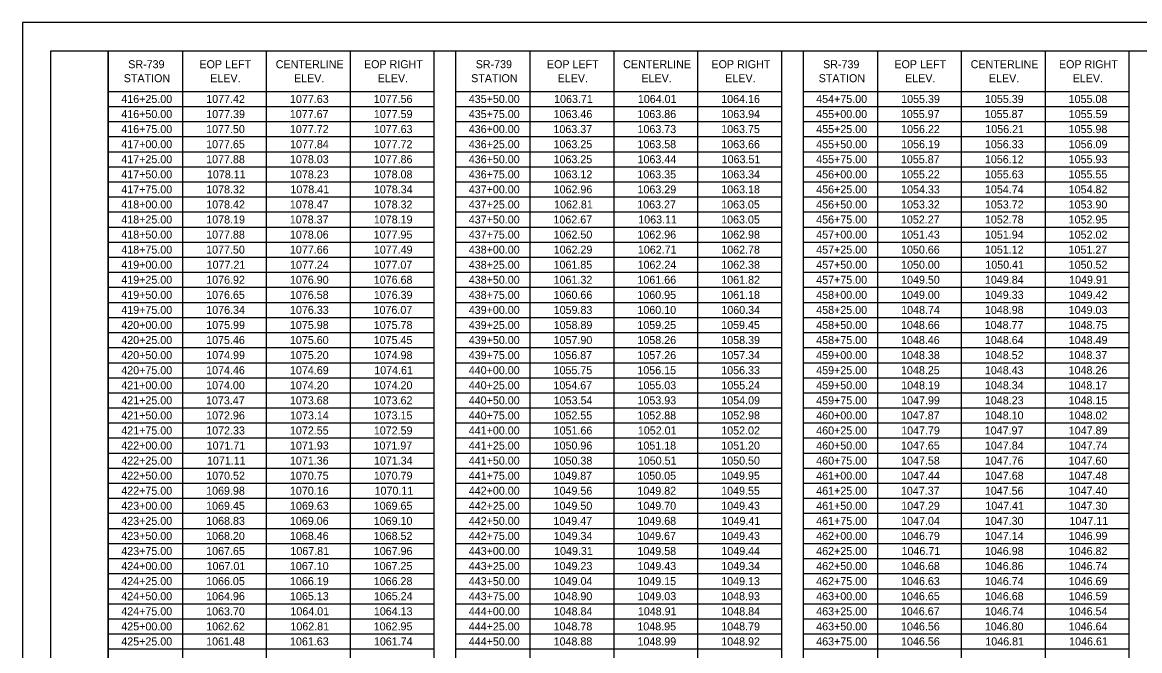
# Model space of a CAD drawing. Extents: x 0 to 34, y 0 to 22.
# Drawn here: x 0 to 19.54, y 11.01 to 22 of the extents above; entities that cross this region are included whole.
import ezdxf

# ---------------------------------------------------------------- set-up
doc = ezdxf.new("R2010")
doc.units = 0
for name, color, linetype in [('SH_Border', 7, 'Continuous'), ('SH_Cut_Line', 7, 'Continuous'), ('SH_Text', 7, 'Continuous')]:
    doc.layers.add(name, color=color, linetype=linetype)

msp = doc.modelspace()

# ---------------------------------------------------------------- linework, layer by layer
at = {"layer": 'SH_Border'}
for points in [[(0.5, 21.5), (1.5, 21.5), (1.5, 0.5), (0.5, 0.5)], [(1.5, 21.5), (33.5, 21.5), (33.5, 0.5), (1.5, 0.5)]]:
    msp.add_lwpolyline(points, close=True, dxfattribs=at)
at = {"layer": 'SH_Cut_Line'}
msp.add_lwpolyline([(0, 0), (34, 0), (34, 22), (0, 22)], close=True, dxfattribs=at)
at = {"layer": 'SH_Text'}
for p, q in [((1.5, 21.5), (7.199, 21.5)), ((1.5, 21.5), (1.5, 0.5)), ((2.801, 21.5), (2.801, 0.5)), ((4.267, 21.5), (4.267, 0.5)), ((5.733, 21.5), (5.733, 0.5)), ((7.199, 21.5), (7.199, 0.5)), ((7.578, 21.5), (13.276, 21.5)), ((7.578, 21.5), (7.578, 0.5)), ((8.879, 21.5), (8.879, 0.5)), ((10.345, 21.5), (10.345, 0.5)), ((11.811, 21.5), (11.811, 0.5)), ((13.276, 21.5), (13.276, 0.5)), ((13.655, 21.5), (19.354, 21.5)), ((13.655, 21.5), (13.655, 0.5)), ((14.956, 21.5), (14.956, 0.5)), ((16.422, 21.5), (16.422, 0.5)), ((17.888, 21.5), (17.888, 0.5)), ((19.354, 21.5), (19.354, 0.5)), ((1.5, 20.792), (7.199, 20.792)), ((7.578, 20.792), (13.276, 20.792)), ((13.655, 20.792), (19.354, 20.792)), ((1.5, 20.528), (7.199, 20.528)), ((7.578, 20.528), (13.276, 20.528)), ((13.655, 20.528), (19.354, 20.528)), ((1.5, 20.265), (7.199, 20.265)), ((7.578, 20.265), (13.276, 20.265)), ((13.655, 20.265), (19.354, 20.265)), ((1.5, 20.001), (7.199, 20.001)), ((7.578, 20.001), (13.276, 20.001)), ((13.655, 20.001), (19.354, 20.001)), ((1.5, 19.738), (7.199, 19.738)), ((7.578, 19.738), (13.276, 19.738)), ((13.655, 19.738), (19.354, 19.738)), ((1.5, 19.474), (7.199, 19.474)), ((7.578, 19.474), (13.276, 19.474)), ((13.655, 19.474), (19.354, 19.474)), ((1.5, 19.211), (7.199, 19.211)), ((7.578, 19.211), (13.276, 19.211)), ((13.655, 19.211), (19.354, 19.211)), ((1.5, 18.947), (7.199, 18.947)), ((7.578, 18.947), (13.276, 18.947)), ((13.655, 18.947), (19.354, 18.947)), ((1.5, 18.684), (7.199, 18.684)), ((7.578, 18.684), (13.276, 18.684)), ((13.655, 18.684), (19.354, 18.684)), ((1.5, 18.42), (7.199, 18.42)), ((7.578, 18.42), (13.276, 18.42)), ((13.655, 18.42), (19.354, 18.42)), ((1.5, 18.156), (7.199, 18.156)), ((7.578, 18.156), (13.276, 18.156)), ((13.655, 18.156), (19.354, 18.156)), ((1.5, 17.893), (7.199, 17.893)), ((7.578, 17.893), (13.276, 17.893)), ((13.655, 17.893), (19.354, 17.893)), ((1.5, 17.629), (7.199, 17.629)), ((7.578, 17.629), (13.276, 17.629)), ((13.655, 17.629), (19.354, 17.629)), ((1.5, 17.366), (7.199, 17.366)), ((7.578, 17.366), (13.276, 17.366)), ((13.655, 17.366), (19.354, 17.366)), ((1.5, 17.102), (7.199, 17.102)), ((7.578, 17.102), (13.276, 17.102)), ((13.655, 17.102), (19.354, 17.102)), ((1.5, 16.839), (7.199, 16.839)), ((7.578, 16.839), (13.276, 16.839)), ((13.655, 16.839), (19.354, 16.839)), ((1.5, 16.575), (7.199, 16.575)), ((7.578, 16.575), (13.276, 16.575)), ((13.655, 16.575), (19.354, 16.575)), ((1.5, 16.312), (7.199, 16.312)), ((7.578, 16.312), (13.276, 16.312)), ((13.655, 16.312), (19.354, 16.312)), ((1.5, 16.048), (7.199, 16.048)), ((7.578, 16.048), (13.276, 16.048)), ((13.655, 16.048), (19.354, 16.048)), ((1.5, 15.785), (7.199, 15.785)), ((7.578, 15.785), (13.276, 15.785)), ((13.655, 15.785), (19.354, 15.785)), ((1.5, 15.521), (7.199, 15.521)), ((7.578, 15.521), (13.276, 15.521)), ((13.655, 15.521), (19.354, 15.521)), ((1.5, 15.258), (7.199, 15.258)), ((7.578, 15.258), (13.276, 15.258)), ((13.655, 15.258), (19.354, 15.258)), ((1.5, 14.994), (7.199, 14.994)), ((7.578, 14.994), (13.276, 14.994)), ((13.655, 14.994), (19.354, 14.994)), ((1.5, 14.731), (7.199, 14.731)), ((7.578, 14.731), (13.276, 14.731)), ((13.655, 14.731), (19.354, 14.731)), ((1.5, 14.467), (7.199, 14.467)), ((7.578, 14.467), (13.276, 14.467)), ((13.655, 14.467), (19.354, 14.467)), ((1.5, 14.204), (7.199, 14.204)), ((7.578, 14.204), (13.276, 14.204)), ((13.655, 14.204), (19.354, 14.204)), ((1.5, 13.94), (7.199, 13.94)), ((7.578, 13.94), (13.276, 13.94)), ((13.655, 13.94), (19.354, 13.94)), ((1.5, 13.676), (7.199, 13.676)), ((7.578, 13.676), (13.276, 13.676)), ((13.655, 13.676), (19.354, 13.676)), ((1.5, 13.413), (7.199, 13.413)), ((7.578, 13.413), (13.276, 13.413)), ((13.655, 13.413), (19.354, 13.413)), ((1.5, 13.149), (7.199, 13.149)), ((7.578, 13.149), (13.276, 13.149)), ((13.655, 13.149), (19.354, 13.149)), ((1.5, 12.886), (7.199, 12.886)), ((7.578, 12.886), (13.276, 12.886)), ((13.655, 12.886), (19.354, 12.886)), ((1.5, 12.622), (7.199, 12.622)), ((7.578, 12.622), (13.276, 12.622)), ((13.655, 12.622), (19.354, 12.622)), ((1.5, 12.359), (7.199, 12.359)), ((7.578, 12.359), (13.276, 12.359)), ((13.655, 12.359), (19.354, 12.359)), ((1.5, 12.095), (7.199, 12.095)), ((7.578, 12.095), (13.276, 12.095)), ((13.655, 12.095), (19.354, 12.095)), ((1.5, 11.832), (7.199, 11.832)), ((7.578, 11.832), (13.276, 11.832)), ((13.655, 11.832), (19.354, 11.832)), ((1.5, 11.568), (7.199, 11.568)), ((7.578, 11.568), (13.276, 11.568)), ((13.655, 11.568), (19.354, 11.568)), ((1.5, 11.305), (7.199, 11.305)), ((7.578, 11.305), (13.276, 11.305)), ((13.655, 11.305), (19.354, 11.305)), ((1.5, 11.041), (7.199, 11.041)), ((7.578, 11.041), (13.276, 11.041)), ((13.655, 11.041), (19.354, 11.041))]:
    msp.add_line(p, q, dxfattribs=at)

# ---------------------------------------------------------------- texts
for s, p in [('SR-739 ', (1.852, 21.198)), ('EOP LEFT ', (3.098, 21.198)), ('CENTERLINE ', (4.433, 21.198)), ('EOP RIGHT ', (5.976, 21.198)), ('SR-739 ', (7.93, 21.198)), ('EOP LEFT ', (9.176, 21.198)), ('CENTERLINE ', (10.51, 21.198)), ('EOP RIGHT ', (12.054, 21.198)), ('SR-739 ', (14.007, 21.198)), ('EOP LEFT ', (15.254, 21.198)), ('CENTERLINE ', (16.588, 21.198)), ('EOP RIGHT ', (18.132, 21.198)), ('STATION', (1.774, 20.953)), ('ELEV.', (3.286, 20.953)), ('ELEV.', (4.752, 20.953)), ('ELEV.', (6.217, 20.953)), ('STATION', (7.851, 20.953)), ('ELEV.', (9.363, 20.953)), ('ELEV.', (10.829, 20.953)), ('ELEV.', (12.295, 20.953)), ('STATION', (13.929, 20.953)), ('ELEV.', (15.441, 20.953)), ('ELEV.', (16.907, 20.953)), ('ELEV.', (18.373, 20.953)), ('416+25.00', (1.731, 20.59)), ('1077.42', (3.216, 20.59)), ('1077.63', (4.682, 20.59)), ('1077.56', (6.147, 20.59)), ('435+50.00', (7.809, 20.59)), ('1063.71', (9.301, 20.59)), ('1064.01', (10.766, 20.59)), ('1064.16', (12.225, 20.59)), ('454+75.00', (13.886, 20.59)), ('1055.39', (15.372, 20.59)), ('1055.39', (16.838, 20.59)), ('1055.08', (18.302, 20.59)), ('416+50.00', (1.731, 20.326)), ('1077.39', (3.217, 20.326)), ('1077.67', (4.679, 20.326)), ('1077.59', (6.148, 20.326)), ('435+75.00', (7.809, 20.326)), ('1063.46', (9.293, 20.326)), ('1063.86', (10.759, 20.326)), ('1063.94', (12.227, 20.326)), ('455+00.00', (13.886, 20.326)), ('1055.97', (15.368, 20.326)), ('1055.87', (16.834, 20.326)), ('1055.59', (18.304, 20.326)), ('416+75.00', (1.731, 20.063)), ('1077.50', (3.215, 20.063)), ('1077.72', (4.681, 20.063)), ('1077.63', (6.148, 20.063)), ('436+00.00', (7.809, 20.063)), ('1063.37', (9.29, 20.063)), ('1063.73', (10.76, 20.063)), ('1063.75', (12.224, 20.063)), ('455+25.00', (13.886, 20.063)), ('1056.22', (15.371, 20.063)), ('1056.21', (16.844, 20.063)), ('1055.98', (18.302, 20.063)), ('417+00.00', (1.731, 19.799)), ('1077.65', (3.215, 19.799)), ('1077.84', (4.683, 19.799)), ('1077.72', (6.147, 19.799)), ('436+25.00', (7.809, 19.799)), ('1063.25', (9.292, 19.799)), ('1063.58', (10.759, 19.799)), ('1063.66', (12.225, 19.799)), ('455+50.00', (13.886, 19.799)), ('1056.19', (15.372, 19.799)), ('1056.33', (16.837, 19.799)), ('1056.09', (18.304, 19.799)), ('417+25.00', (1.731, 19.536)), ('1077.88', (3.215, 19.536)), ('1078.03', (4.682, 19.536)), ('1077.86', (6.147, 19.536)), ('436+50.00', (7.809, 19.536)), ('1063.25', (9.292, 19.536)), ('1063.44', (10.761, 19.536)), ('1063.51', (12.232, 19.536)), ('455+75.00', (13.886, 19.536)), ('1055.87', (15.368, 19.536)), ('1056.12', (16.837, 19.536)), ('1055.93', (18.303, 19.536)), ('417+50.00', (1.731, 19.272)), ('1078.11', (3.229, 19.272)), ('1078.23', (4.682, 19.272)), ('1078.08', (6.147, 19.272)), ('436+75.00', (7.809, 19.272)), ('1063.12', (9.293, 19.272)), ('1063.35', (10.758, 19.272)), ('1063.34', (12.227, 19.272)), ('456+00.00', (13.886, 19.272)), ('1055.22', (15.371, 19.272)), ('1055.63', (16.837, 19.272)), ('1055.55', (18.302, 19.272)), ('417+75.00', (1.731, 19.009)), ('1078.32', (3.216, 19.009)), ('1078.41', (4.689, 19.009)), ('1078.34', (6.149, 19.009)), ('437+00.00', (7.809, 19.009)), ('1062.96', (9.293, 19.009)), ('1063.29', (10.76, 19.009)), ('1063.18', (12.225, 19.009)), ('456+25.00', (13.886, 19.009)), ('1054.33', (15.371, 19.009)), ('1054.74', (16.838, 19.009)), ('1054.82', (18.303, 19.009)), ('418+00.00', (1.731, 18.745)), ('1078.42', (3.216, 18.745)), ('1078.47', (4.679, 18.745)), ('1078.32', (6.147, 18.745)), ('437+25.00', (7.809, 18.745)), ('1062.81', (9.301, 18.745)), ('1063.27', (10.756, 18.745)), ('1063.05', (12.224, 18.745)), ('456+50.00', (13.886, 18.745)), ('1053.32', (15.371, 18.745)), ('1053.72', (16.837, 18.745)), ('1053.90', (18.302, 18.745)), ('418+25.00', (1.731, 18.482)), ('1078.19', (3.217, 18.482)), ('1078.37', (4.679, 18.482)), ('1078.19', (6.148, 18.482)), ('437+50.00', (7.809, 18.482)), ('1062.67', (9.29, 18.482)), ('1063.11', (10.773, 18.482)), ('1063.05', (12.224, 18.482)), ('456+75.00', (13.886, 18.482)), ('1052.27', (15.368, 18.482)), ('1052.78', (16.837, 18.482)), ('1052.95', (18.302, 18.482)), ('418+50.00', (1.731, 18.218)), ('1077.88', (3.215, 18.218)), ('1078.06', (4.681, 18.218)), ('1077.95', (6.146, 18.218)), ('437+75.00', (7.809, 18.218)), ('1062.50', (9.293, 18.218)), ('1062.96', (10.759, 18.218)), ('1062.98', (12.225, 18.218)), ('457+00.00', (13.886, 18.218)), ('1051.43', (15.371, 18.218)), ('1051.94', (16.838, 18.218)), ('1052.02', (18.303, 18.218)), ('418+75.00', (1.731, 17.955)), ('1077.50', (3.215, 17.955)), ('1077.66', (4.681, 17.955)), ('1077.49', (6.148, 17.955)), ('438+00.00', (7.809, 17.955)), ('1062.29', (9.294, 17.955)), ('1062.71', (10.766, 17.955)), ('1062.78', (12.225, 17.955)), ('457+25.00', (13.886, 17.955)), ('1050.66', (15.37, 17.955)), ('1051.12', (16.837, 17.955)), ('1051.27', (18.3, 17.955)), ('419+00.00', (1.731, 17.691)), ('1077.21', (3.223, 17.691)), ('1077.24', (4.683, 17.691)), ('1077.07', (6.144, 17.691)), ('438+25.00', (7.809, 17.691)), ('1061.85', (9.292, 17.691)), ('1062.24', (10.761, 17.691)), ('1062.38', (12.225, 17.691)), ('457+50.00', (13.886, 17.691)), ('1050.00', (15.371, 17.691)), ('1050.41', (16.844, 17.691)), ('1050.52', (18.303, 17.691)), ('419+25.00', (1.731, 17.428)), ('1076.92', (3.216, 17.428)), ('1076.90', (4.681, 17.428)), ('1076.68', (6.147, 17.428)), ('438+50.00', (7.809, 17.428)), ('1061.32', (9.293, 17.428)), ('1061.66', (10.759, 17.428)), ('1061.82', (12.225, 17.428)), ('457+75.00', (13.886, 17.428)), ('1049.50', (15.371, 17.428)), ('1049.84', (16.838, 17.428)), ('1049.91', (18.31, 17.428)), ('419+50.00', (1.731, 17.164)), ('1076.65', (3.215, 17.164)), ('1076.58', (4.681, 17.164)), ('1076.39', (6.148, 17.164)), ('438+75.00', (7.809, 17.164)), ('1060.66', (9.293, 17.164)), ('1060.95', (10.758, 17.164)), ('1061.18', (12.225, 17.164)), ('458+00.00', (13.886, 17.164)), ('1049.00', (15.371, 17.164)), ('1049.33', (16.837, 17.164)), ('1049.42', (18.303, 17.164)), ('419+75.00', (1.731, 16.901)), ('1076.34', (3.217, 16.901)), ('1076.33', (4.682, 16.901)), ('1076.07', (6.144, 16.901)), ('439+00.00', (7.809, 16.901)), ('1059.83', (9.294, 16.901)), ('1060.10', (10.759, 16.901)), ('1060.34', (12.227, 16.901)), ('458+25.00', (13.886, 16.901)), ('1048.74', (15.372, 16.901)), ('1048.98', (16.837, 16.901)), ('1049.03', (18.303, 16.901)), ('420+00.00', (1.731, 16.637)), ('1075.99', (3.217, 16.637)), ('1075.98', (4.681, 16.637)), ('1075.78', (6.147, 16.637)), ('439+25.00', (7.809, 16.637)), ('1058.89', (9.294, 16.637)), ('1059.25', (10.758, 16.637)), ('1059.45', (12.224, 16.637)), ('458+50.00', (13.886, 16.637)), ('1048.66', (15.37, 16.637)), ('1048.77', (16.834, 16.637)), ('1048.75', (18.302, 16.637)), ('420+25.00', (1.731, 16.374)), ('1075.46', (3.215, 16.374)), ('1075.60', (4.681, 16.374)), ('1075.45', (6.146, 16.374)), ('439+50.00', (7.809, 16.374)), ('1057.90', (9.293, 16.374)), ('1058.26', (10.759, 16.374)), ('1058.39', (12.226, 16.374)), ('458+75.00', (13.886, 16.374)), ('1048.46', (15.37, 16.374)), ('1048.64', (16.838, 16.374)), ('1048.49', (18.304, 16.374)), ('420+50.00', (1.731, 16.11)), ('1074.99', (3.217, 16.11)), ('1075.20', (4.681, 16.11)), ('1074.98', (6.147, 16.11)), ('439+75.00', (7.809, 16.11)), ('1056.87', (9.29, 16.11)), ('1057.26', (10.759, 16.11)), ('1057.34', (12.227, 16.11)), ('459+00.00', (13.886, 16.11)), ('1048.38', (15.371, 16.11)), ('1048.52', (16.837, 16.11)), ('1048.37', (18.3, 16.11)), ('420+75.00', (1.731, 15.846)), ('1074.46', (3.215, 15.846)), ('1074.69', (4.682, 15.846)), ('1074.61', (6.155, 15.846)), ('440+00.00', (7.809, 15.846)), ('1055.75', (9.292, 15.846)), ('1056.15', (10.758, 15.846)), ('1056.33', (12.225, 15.846)), ('459+25.00', (13.886, 15.846)), ('1048.25', (15.37, 15.846)), ('1048.43', (16.837, 15.846)), ('1048.26', (18.302, 15.846)), ('421+00.00', (1.731, 15.583)), ('1074.00', (3.215, 15.583)), ('1074.20', (4.681, 15.583)), ('1074.20', (6.147, 15.583)), ('440+25.00', (7.809, 15.583)), ('1054.67', (9.29, 15.583)), ('1055.03', (10.76, 15.583)), ('1055.24', (12.227, 15.583)), ('459+50.00', (13.886, 15.583)), ('1048.19', (15.372, 15.583)), ('1048.34', (16.838, 15.583)), ('1048.17', (18.3, 15.583)), ('421+25.00', (1.731, 15.319)), ('1073.47', (3.213, 15.319)), ('1073.68', (4.681, 15.319)), ('1073.62', (6.147, 15.319)), ('440+50.00', (7.809, 15.319)), ('1053.54', (9.295, 15.319)), ('1053.93', (10.76, 15.319)), ('1054.09', (12.226, 15.319)), ('459+75.00', (13.886, 15.319)), ('1047.99', (15.372, 15.319)), ('1048.23', (16.837, 15.319)), ('1048.15', (18.302, 15.319)), ('421+50.00', (1.731, 15.056)), ('1072.96', (3.215, 15.056)), ('1073.14', (4.683, 15.056)), ('1073.15', (6.146, 15.056)), ('440+75.00', (7.809, 15.056)), ('1052.55', (9.292, 15.056)), ('1052.88', (10.759, 15.056)), ('1052.98', (12.225, 15.056)), ('460+00.00', (13.886, 15.056)), ('1047.87', (15.368, 15.056)), ('1048.10', (16.836, 15.056)), ('1048.02', (18.303, 15.056)), ('421+75.00', (1.731, 14.792)), ('1072.33', (3.216, 14.792)), ('1072.55', (4.681, 14.792)), ('1072.59', (6.148, 14.792)), ('441+00.00', (7.809, 14.792)), ('1051.66', (9.293, 14.792)), ('1052.01', (10.766, 14.792)), ('1052.02', (12.225, 14.792)), ('460+25.00', (13.886, 14.792)), ('1047.79', (15.372, 14.792)), ('1047.97', (16.834, 14.792)), ('1047.89', (18.304, 14.792)), ('422+00.00', (1.731, 14.529)), ('1071.71', (3.223, 14.529)), ('1071.93', (4.682, 14.529)), ('1071.97', (6.144, 14.529)), ('441+25.00', (7.809, 14.529)), ('1050.96', (9.293, 14.529)), ('1051.18', (10.759, 14.529)), ('1051.20', (12.225, 14.529)), ('460+50.00', (13.886, 14.529)), ('1047.65', (15.37, 14.529)), ('1047.84', (16.838, 14.529)), ('1047.74', (18.304, 14.529)), ('422+25.00', (1.731, 14.265)), ('1071.11', (3.229, 14.265)), ('1071.36', (4.681, 14.265)), ('1071.34', (6.149, 14.265)), ('441+50.00', (7.809, 14.265)), ('1050.38', (9.293, 14.265)), ('1050.51', (10.766, 14.265)), ('1050.50', (12.225, 14.265)), ('460+75.00', (13.886, 14.265)), ('1047.58', (15.371, 14.265)), ('1047.76', (16.836, 14.265)), ('1047.60', (18.302, 14.265)), ('422+50.00', (1.731, 14.002)), ('1070.52', (3.216, 14.002)), ('1070.75', (4.681, 14.002)), ('1070.79', (6.148, 14.002)), ('441+75.00', (7.809, 14.002)), ('1049.87', (9.29, 14.002)), ('1050.05', (10.758, 14.002)), ('1049.95', (12.224, 14.002)), ('461+00.00', (13.886, 14.002)), ('1047.44', (15.372, 14.002)), ('1047.68', (16.837, 14.002)), ('1047.48', (18.302, 14.002)), ('422+75.00', (1.731, 13.738)), ('1069.98', (3.215, 13.738)), ('1070.16', (4.681, 13.738)), ('1070.11', (6.161, 13.738)), ('442+00.00', (7.809, 13.738)), ('1049.56', (9.293, 13.738)), ('1049.82', (10.759, 13.738)), ('1049.55', (12.224, 13.738)), ('461+25.00', (13.886, 13.738)), ('1047.37', (15.368, 13.738)), ('1047.56', (16.836, 13.738)), ('1047.40', (18.302, 13.738)), ('423+00.00', (1.731, 13.475)), ('1069.45', (3.215, 13.475)), ('1069.63', (4.682, 13.475)), ('1069.65', (6.146, 13.475)), ('442+25.00', (7.809, 13.475)), ('1049.50', (9.293, 13.475)), ('1049.70', (10.759, 13.475)), ('1049.43', (12.225, 13.475)), ('461+50.00', (13.886, 13.475)), ('1047.29', (15.372, 13.475)), ('1047.41', (16.844, 13.475)), ('1047.30', (18.302, 13.475)), ('423+25.00', (1.731, 13.211)), ('1068.83', (3.216, 13.211)), ('1069.06', (4.681, 13.211)), ('1069.10', (6.147, 13.211)), ('442+50.00', (7.809, 13.211)), ('1049.47', (9.29, 13.211)), ('1049.68', (10.759, 13.211)), ('1049.41', (12.232, 13.211)), ('461+75.00', (13.886, 13.211)), ('1047.04', (15.372, 13.211)), ('1047.30', (16.836, 13.211)), ('1047.11', (18.316, 13.211)), ('423+50.00', (1.731, 12.948)), ('1068.20', (3.215, 12.948)), ('1068.46', (4.681, 12.948)), ('1068.52', (6.147, 12.948)), ('442+75.00', (7.809, 12.948)), ('1049.34', (9.295, 12.948)), ('1049.67', (10.756, 12.948)), ('1049.43', (12.225, 12.948)), ('462+00.00', (13.886, 12.948)), ('1046.79', (15.372, 12.948)), ('1047.14', (16.838, 12.948)), ('1046.99', (18.304, 12.948)), ('423+75.00', (1.731, 12.684)), ('1067.65', (3.215, 12.684)), ('1067.81', (4.689, 12.684)), ('1067.96', (6.147, 12.684)), ('443+00.00', (7.809, 12.684)), ('1049.31', (9.301, 12.684)), ('1049.58', (10.759, 12.684)), ('1049.44', (12.227, 12.684)), ('462+25.00', (13.886, 12.684)), ('1046.71', (15.378, 12.684)), ('1046.98', (16.837, 12.684)), ('1046.82', (18.303, 12.684)), ('424+00.00', (1.731, 12.421)), ('1067.01', (3.223, 12.421)), ('1067.10', (4.681, 12.421)), ('1067.25', (6.146, 12.421)), ('443+25.00', (7.809, 12.421)), ('1049.23', (9.294, 12.421)), ('1049.43', (10.76, 12.421)), ('1049.34', (12.227, 12.421)), ('462+50.00', (13.886, 12.421)), ('1046.68', (15.371, 12.421)), ('1046.86', (16.836, 12.421)), ('1046.74', (18.304, 12.421)), ('424+25.00', (1.731, 12.157)), ('1066.05', (3.215, 12.157)), ('1066.19', (4.682, 12.157)), ('1066.28', (6.147, 12.157)), ('443+50.00', (7.809, 12.157)), ('1049.04', (9.295, 12.157)), ('1049.15', (10.758, 12.157)), ('1049.13', (12.225, 12.157)), ('462+75.00', (13.886, 12.157)), ('1046.63', (15.371, 12.157)), ('1046.74', (16.838, 12.157)), ('1046.69', (18.304, 12.157)), ('424+50.00', (1.731, 11.894)), ('1064.96', (3.215, 11.894)), ('1065.13', (4.682, 11.894)), ('1065.24', (6.149, 11.894)), ('443+75.00', (7.809, 11.894)), ('1048.90', (9.293, 11.894)), ('1049.03', (10.76, 11.894)), ('1048.93', (12.225, 11.894)), ('463+00.00', (13.886, 11.894)), ('1046.65', (15.37, 11.894)), ('1046.68', (16.837, 11.894)), ('1046.59', (18.304, 11.894)), ('424+75.00', (1.731, 11.63)), ('1063.70', (3.215, 11.63)), ('1064.01', (4.689, 11.63)), ('1064.13', (6.148, 11.63)), ('444+00.00', (7.809, 11.63)), ('1048.84', (9.295, 11.63)), ('1048.91', (10.766, 11.63)), ('1048.84', (12.227, 11.63)), ('463+25.00', (13.886, 11.63)), ('1046.67', (15.368, 11.63)), ('1046.74', (16.838, 11.63)), ('1046.54', (18.304, 11.63)), ('425+00.00', (1.731, 11.366)), ('1062.62', (3.216, 11.366)), ('1062.81', (4.689, 11.366)), ('1062.95', (6.146, 11.366)), ('444+25.00', (7.809, 11.366)), ('1048.78', (9.293, 11.366)), ('1048.95', (10.758, 11.366)), ('1048.79', (12.226, 11.366)), ('463+50.00', (13.886, 11.366)), ('1046.56', (15.37, 11.366)), ('1046.80', (16.836, 11.366)), ('1046.64', (18.304, 11.366)), ('425+25.00', (1.731, 11.103)), ('1061.48', (3.215, 11.103)), ('1061.63', (4.682, 11.103)), ('1061.74', (6.149, 11.103)), ('444+50.00', (7.809, 11.103)), ('1048.88', (9.293, 11.103)), ('1048.99', (10.76, 11.103)), ('1048.92', (12.225, 11.103)), ('463+75.00', (13.886, 11.103)), ('1046.56', (15.37, 11.103)), ('1046.81', (16.844, 11.103)), ('1046.61', (18.31, 11.103))]:
    msp.add_text(s, height=0.14, dxfattribs=at).set_placement(p)

doc.saveas('drawing.dxf')
